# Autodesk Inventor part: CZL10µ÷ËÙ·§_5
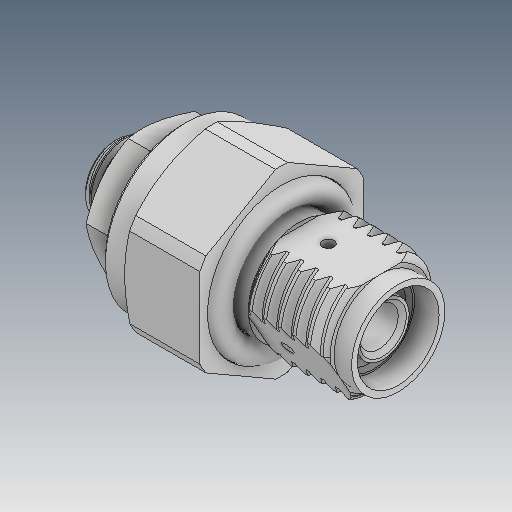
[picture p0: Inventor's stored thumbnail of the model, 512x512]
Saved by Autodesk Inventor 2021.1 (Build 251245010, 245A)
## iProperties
Created: 2019-04
Part Number: CZL10µ÷ËÙ·§_5
Material: Ogólny
Document SubType Name: Modeling
Designer: user
Density: 1 g/cm^3
Appearance: Domyślna
Author: user
Revision Number: ÈÎºÎ
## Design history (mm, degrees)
feature "ÊäÈë3"
feature "ÊäÈë4"
feature "ÊäÈë5"
node "Bryła1"
node "Bryła2"
node "Bryła3"
